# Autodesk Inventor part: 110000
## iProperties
Shininess: 64.0
Length Units: 11272
Angle Units: 11279
Time Units: 11290
Mass Units: 11286
Length Display Precision: 3
Angle Display Precision: 2
Compacted: True
Part Number: 110000
Document SubType Name: Modeling
Created: 2004-06
Designer: jpittman
Manufacturer: Standard
Standards Organization: Custom
Density: 0.0
Volumn: 0.0
Area: 0.0
PropertySet Name: Model Information
Control State: 0
Master: False
Checked Out: False
Translation Standard: STEP AP203
File Name: 110000
Preprocessor: PRO/ENGINEER BY PARAMETRIC TECHNOLOGY CORPORATION, 2001150
Postprocessor: Build: 081d, Release: 8 SP1 - Date: Tue 01/26/2004
Sent Units: INCHES
Uncertainty: 0.00019022974225369998
Author: jpittman
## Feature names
1. Base1
